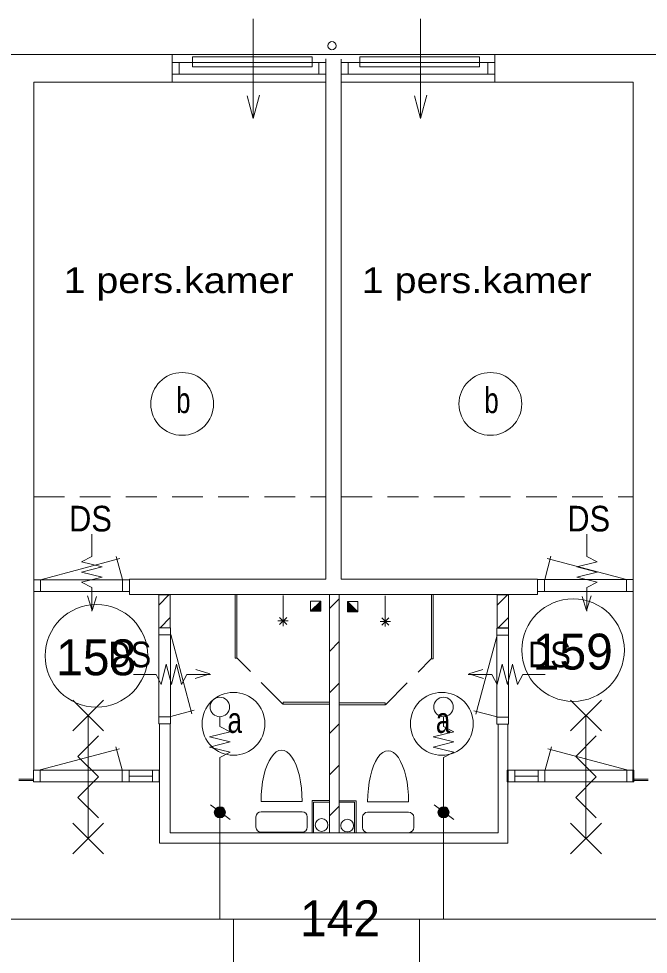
# Model space of a CAD drawing. Extents: x 295824 to 414724, y 24924 to 109024.
# Drawn here: x 313944 to 320086, y 70382 to 79510 of the extents above; entities that cross this region are included whole.
import ezdxf
from ezdxf.enums import TextEntityAlignment as Align

# ---------------------------------------------------------------- set-up
doc = ezdxf.new("R2010")
doc.units = 0
doc.header["$LTSCALE"] = 100
doc.linetypes.add('MEDIUM_DASHED', pattern=[4.5, 3, -1.5])
for name, color, linetype, lineweight in [('1', 7, 'Continuous', 13), ('16', 7, 'Continuous', 13), ('24', 7, 'Continuous', 13), ('61', 7, 'Continuous', 13)]:
    doc.layers.add(name, color=color, linetype=linetype, lineweight=lineweight)

msp = doc.modelspace()

# ---------------------------------------------------------------- hatches: boundary and pattern name
at = {"layer": '24'}
for points in [[(315960.8, 71768.1, 1), (315852.2, 71768.1, 1)], [(318142.8, 71768.1, 1), (318034.2, 71768.1, 1)]]:
    msp.add_hatch(color=256, dxfattribs=at).paths.add_polyline_path(points)
at = {"layer": '61'}
for points in [[(316790.6, 73728.2), (316890.6, 73828.2), (316890.6, 73728.2)], [(317253, 73722.8), (317153, 73822.8), (317153, 73722.8)]]:
    msp.add_hatch(color=256, dxfattribs=at).paths.add_polyline_path(points)

# ---------------------------------------------------------------- linework, layer by layer
at = {"layer": '1'}
for p, q in [((315906.5, 71736.8), (315906.5, 70726.3)), ((318088.5, 71730.1), (318088.5, 70726.3)), ((316039.8, 69843.4), (316039.8, 70726.3)), ((317855.3, 69838.4), (317855.3, 70726.3))]:
    msp.add_line(p, q, dxfattribs=at)
at = {"layer": '16'}
for p, q in [((314557.3, 74111.7), (314757.3, 74161.7)), ((319587.6, 74111.7), (319387.6, 74161.7)), ((315433.7, 73013.5), (315383.7, 73213.5)), ((318711.2, 73013.5), (318761.2, 73213.5))]:
    msp.add_line(p, q, dxfattribs=at)
at = {"layer": '24'}
for p, q in [((316231.3, 78534.5), (316171.7, 78756.9)), ((317863.6, 78534.5), (317804, 78756.9)), ((314660.7, 73736.3), (314615.7, 73880.4)), ((314703.1, 73872.1), (314660.7, 73736.3)), ((319441.8, 73872.1), (319484.2, 73736.3)), ((319484.2, 73736.3), (319529.2, 73880.4)), ((315809.1, 73116.9), (315665, 73071.9)), ((315673.3, 73159.3), (315809.1, 73116.9)), ((318471.6, 73159.3), (318335.8, 73116.9)), ((318335.8, 73116.9), (318480, 73071.9)), ((315906.5, 72253.5), (315906.5, 71714.1)), ((318088.5, 72253.5), (318088.5, 71745.1)), ((315814.9, 71838.9), (316006.4, 71697.3)), ((317996.9, 71838.9), (318188.4, 71697.3)), ((304097.2, 70726.3), (328693.9, 70726.3))]:
    msp.add_line(p, q, dxfattribs=at)
for points in [[(316231.3, 79509.5), (316231.3, 78534.5), (316293, 78764.7)], [(317863.6, 79509.5), (317863.6, 78534.5), (317925.3, 78764.7)], [(314757.3, 74161.7), (314557.3, 74211.7), (314657.3, 74261.7), (314657.3, 74480.4)], [(319387.6, 74161.7), (319587.6, 74211.7), (319487.6, 74261.7), (319487.6, 74480.4)], [(314657.3, 73730.4), (314657.3, 73961.7), (314557.3, 74011.7), (314757.3, 74061.7), (314557.3, 74111.7)], [(319487.6, 73730.4), (319487.6, 73961.7), (319587.6, 74011.7), (319387.6, 74061.7), (319587.6, 74111.7)], [(315383.7, 73213.5), (315333.7, 73013.5), (315283.7, 73113.5), (315065, 73113.5)], [(315815, 73113.5), (315583.7, 73113.5), (315533.7, 73013.5), (315483.7, 73213.5), (315433.7, 73013.5)], [(318330, 73113.5), (318561.2, 73113.5), (318611.2, 73013.5), (318661.2, 73213.5), (318711.2, 73013.5)], [(318761.2, 73213.5), (318811.2, 73013.5), (318861.2, 73113.5), (319079.9, 73113.5)], [(315906.5, 72703.5), (315906.5, 72603.5), (316006.5, 72553.5), (315806.5, 72503.5), (316006.5, 72453.5), (315806.5, 72403.5), (316006.5, 72353.5), (315906.5, 72303.5), (315906.5, 72253.5)], [(318088.5, 72703.5), (318088.5, 72603.5), (318188.5, 72553.5), (317988.5, 72503.5), (318188.5, 72453.5), (317988.5, 72403.5), (318188.5, 72353.5), (318088.5, 72303.5), (318088.5, 72253.5)]]:
    msp.add_lwpolyline(points, dxfattribs=at)
for points in [[(315640, 79038.7), (316805.9, 79038.7), (316805.9, 79138.7), (315640, 79138.7)], [(317272.3, 79038.7), (318438.2, 79038.7), (318438.2, 79138.7), (317272.3, 79138.7)]]:
    msp.add_lwpolyline(points, close=True, dxfattribs=at)
for centre, radius in [((315906.5, 72795.2), 95), ((318088.5, 72795.2), 95), ((315906.5, 71768.1), 54.3), ((318088.5, 71768.1), 54.3)]:
    msp.add_circle(centre, radius, dxfattribs=at)
at = {"layer": '61'}
for p, q in [((315441, 78890.7), (315441, 79160.7)), ((318589.5, 78890.8), (318589.5, 79160.8)), ((315508, 78969), (315508, 79082.9)), ((316873.1, 78968.4), (316873.1, 79082.4)), ((316940.1, 79118.1), (316940.1, 74040.8)), ((317090.1, 79114.3), (317090.1, 74040.8)), ((317156.6, 78969.4), (317156.6, 79083.4)), ((318520.9, 78969.1), (318520.9, 79082.7)), ((314090.1, 78890.8), (316940.1, 78890.8)), ((314090.1, 72179.8), (314090.1, 78890.8)), ((319940.1, 78890.8), (317090.1, 78890.8)), ((319940.1, 72179.8), (319940.1, 78890.8)), ((314157.5, 74036.8), (314930.2, 74243.8)), ((314955.9, 74037.4), (314895.1, 74264.3)), ((319075.3, 74038.5), (319136, 74265.4)), ((319873.7, 74037.9), (319100.9, 74244.9)), ((314158.2, 73922.2), (314158.2, 74036.2)), ((314958.2, 73922.2), (314958.2, 74036.2)), ((315025.2, 73922.2), (315025.2, 74036.2)), ((319005.9, 73923.2), (319005.9, 74037.2)), ((319072.9, 73923.2), (319072.9, 74037.2)), ((319872.9, 73923.2), (319872.9, 74037.2)), ((315310.4, 73789.9), (315410.1, 73889.6)), ((315311.9, 73566.1), (315311.9, 73890.2)), ((315311.9, 73890.2), (315421.9, 73890.2)), ((315421.9, 73566.1), (315421.9, 73890.2)), ((316073.1, 73890.5), (316073.1, 73270)), ((316523, 73684), (316523, 73884)), ((316975, 73890.8), (316975, 71565.8)), ((316975.5, 73754.6), (317071.3, 73850.4)), ((317071.3, 73890.8), (317071.3, 71565.8)), ((317520.7, 73678.6), (317520.7, 73878.6)), ((317970.5, 73885.1), (317970.5, 73264.6)), ((318610.9, 73566.1), (318610.9, 73890.2)), ((318610.9, 73890.2), (318720.8, 73890.2)), ((318612.6, 73789.9), (318712.3, 73889.6)), ((318720.8, 73566.1), (318720.8, 73890.2)), ((315322.7, 73567.3), (315422.4, 73667)), ((316558.3, 73669.3), (316487.6, 73598.6)), ((316558.3, 73598.6), (316487.6, 73669.3)), ((316523, 73684), (316523, 73584)), ((317485.3, 73664), (317556, 73593.3)), ((317485.3, 73593.3), (317556, 73664)), ((317520.7, 73678.6), (317520.7, 73578.6)), ((318621.2, 73567.3), (318720.9, 73667)), ((315310.1, 73565.2), (315310.1, 72632.8)), ((315311.9, 73566.1), (315421.9, 73566.1)), ((316573, 73634), (316473, 73634)), ((317470.7, 73628.6), (317570.7, 73628.6)), ((318610.9, 73566.1), (318720.8, 73566.1)), ((315310.1, 73499.8), (315424.1, 73499.8)), ((315427.3, 73500.6), (315634.3, 72727.8)), ((318611.5, 73496.3), (318404.4, 72723.6)), ((318723.6, 73495.6), (318609.6, 73495.6)), ((318610.2, 73562.6), (318724.2, 73562.6)), ((318723.6, 73562.6), (318723.6, 72628.6)), ((316975.5, 73336.5), (317071.3, 73432.3)), ((316975.5, 72931.9), (317071.3, 73027.7)), ((314772.1, 72863), (314472.1, 72563)), ((314472.1, 72863), (314772.1, 72563)), ((316973.2, 72840.5), (316524, 72840.5)), ((316524, 72822.5), (316524, 72840.5)), ((317070.5, 72835.1), (317519.6, 72835.1)), ((317519.6, 72817.1), (317519.6, 72835.1)), ((319628, 72863), (319328, 72563)), ((319328, 72863), (319628, 72563)), ((315427.9, 72702.2), (315654.8, 72762.9)), ((316973.5, 72822.5), (316524, 72822.5)), ((317070.2, 72817.1), (317519.6, 72817.1)), ((318610.9, 72697.9), (318384, 72758.7)), ((314622.1, 71513), (314622.1, 72713)), ((315310.1, 72699.8), (315424.1, 72699.8)), ((318723.6, 72695.6), (318609.6, 72695.6)), ((319478, 71513), (319478, 72713)), ((315316.1, 72629.2), (315316.1, 72063.4)), ((315316.1, 72629.2), (315421.3, 72629.2)), ((316975.5, 72535.9), (317071.3, 72631.7)), ((318621.3, 72627.8), (318621.3, 71565.8)), ((318621.3, 72627.8), (318716.1, 72627.8)), ((318716.1, 72627.8), (318716.1, 72165.8)), ((314154.1, 72180.4), (314926.8, 72387.5)), ((314952.5, 72181), (314891.7, 72407.9)), ((319079.8, 72181.1), (319140.6, 72407.9)), ((319878.3, 72180.4), (319105.5, 72387.5)), ((316975.5, 72132.6), (317071.3, 72228.3)), ((314154.9, 72065.8), (314154.9, 72179.8)), ((314954.9, 72065.8), (314954.9, 72179.8)), ((315021.9, 72065.8), (315021.9, 72179.8)), ((315247.9, 72119.9), (315021.9, 72119.9)), ((315247.9, 72065.8), (315247.9, 72179.8)), ((318784.5, 72065.8), (318784.5, 72179.8)), ((318784.5, 72119.9), (319010.5, 72119.9)), ((319010.5, 72065.8), (319010.5, 72179.8)), ((319077.5, 72065.8), (319077.5, 72179.8)), ((319877.5, 72065.8), (319877.5, 72179.8)), ((313944.8, 72092.1), (314086, 72092.1)), ((313944.8, 72077.1), (314086, 72077.1)), ((319943.6, 72092.1), (320084.8, 72092.1)), ((319943.6, 72077.1), (320084.8, 72077.1)), ((316708.7, 71873.6), (316308.7, 71873.6)), ((316821.2, 71866.2), (316971.2, 71866.2)), ((316821.2, 71566.2), (316821.2, 71866.2)), ((317071.3, 71865.8), (317221.3, 71865.8)), ((317221.3, 71865.8), (317221.3, 71565.8)), ((317748.1, 71868.7), (317348.1, 71868.7)), ((316308.7, 71773.6), (316708.7, 71773.6)), ((316975.5, 71731.7), (317071.3, 71827.4)), ((317348.1, 71768.7), (317748.1, 71768.7)), ((314772.1, 71663), (314472.1, 71363)), ((314472.1, 71663), (314772.1, 71363)), ((316258.7, 71623.6), (316258.7, 71723.6)), ((316758.7, 71723.6), (316758.7, 71623.6)), ((317298.1, 71618.7), (317298.1, 71718.7)), ((317798.1, 71718.7), (317798.1, 71618.7)), ((319628, 71663), (319328, 71363)), ((319328, 71663), (319628, 71363)), ((316708.7, 71573.6), (316308.7, 71573.6)), ((317748.1, 71568.7), (317348.1, 71568.7))]:
    msp.add_line(p, q, dxfattribs=at)
at = {"layer": '61', "linetype": 'MEDIUM_DASHED'}
for p, q in [((314090.7, 74844.1), (316939.8, 74844.1)), ((317093.1, 74844.1), (319940.1, 74844.1)), ((316522, 72822.9), (316075.1, 73269.8)), ((317521.7, 72817.6), (317968.6, 73264.5))]:
    msp.add_line(p, q, dxfattribs=at)
at = {"layer": '61'}
for points in [[(301796.6, 66927.7), (301820.1, 79160.8), (332210.1, 79160.8)], [(314091.2, 73922.2), (314091.2, 74036.2), (315025.2, 74036.2)], [(315025.2, 73922.2), (314091.2, 73922.2), (314091.2, 74036.2)], [(316941.1, 74040.8), (315026, 74040.8), (315026, 73890.8), (319005.4, 73890.8)], [(317091.1, 74040.8), (319005.4, 74040.8), (319005.4, 73890.8)], [(319939.9, 73923.2), (319939.9, 74037.2), (319005.9, 74037.2)], [(319005.9, 73923.2), (319939.9, 73923.2), (319939.9, 74037.2)], [(316055.1, 73890.5), (316055.1, 73270), (316073.1, 73270)], [(317988.5, 73885.1), (317988.5, 73264.6), (317970.5, 73264.6)], [(316890.6, 73828.2), (316890.6, 73728.2), (316790.6, 73728.2)], [(317153, 73822.8), (317153, 73722.8), (317253, 73722.8)], [(315421.3, 72629.2), (315421.3, 71565.8), (318621.3, 71565.8)], [(314722.1, 71713), (314522.1, 71913), (314722.1, 72113), (314522.1, 72313), (314722.1, 72513)], [(319578, 71713), (319378, 71913), (319578, 72113), (319378, 72313), (319578, 72513)], [(315316.1, 72065.8), (315316.1, 71465.8), (318716.1, 71465.8), (318716.1, 72065.8)], [(316806.2, 71566.2), (316806.2, 71881.2), (316971.2, 71881.2)], [(317071.3, 71880.8), (317236.3, 71880.8), (317236.3, 71565.8)]]:
    msp.add_lwpolyline(points, dxfattribs=at)
for points in [[(315441.2, 78968.9), (315441.2, 79082.9), (316939.9, 79082.9), (316939.9, 78968.9)], [(317090.2, 78969.1), (317090.2, 79083.1), (318589.6, 79083.1), (318589.6, 78969.1)], [(316890.6, 73828.2), (316790.6, 73828.2), (316790.6, 73728.2)], [(316790.6, 73728.2), (316890.6, 73828.2), (316890.6, 73728.2)], [(317153, 73822.8), (317253, 73822.8), (317253, 73722.8)], [(317253, 73722.8), (317153, 73822.8), (317153, 73722.8)], [(315310.1, 72631.9), (315424.1, 72631.9), (315424.1, 73565.9), (315310.1, 73565.9)], [(318723.6, 73562.6), (318723.6, 72628.6), (318609.6, 72628.6), (318609.6, 73562.6)], [(314087.9, 72065.8), (314087.9, 72179.8), (315314.2, 72179.8), (315314.2, 72065.8)], [(314087.9, 72065.8), (314087.9, 72179.8), (315314.2, 72179.8), (315314.2, 72065.8)], [(318709.2, 72065.8), (318709.2, 72179.8), (319936.2, 72179.8), (319936.2, 72065.8)], [(318717.5, 72065.8), (318717.5, 72179.8), (319944.5, 72179.8), (319944.5, 72065.8)]]:
    msp.add_lwpolyline(points, close=True, dxfattribs=at)
for centre, radius in [((317000.1, 79245.8), 40), ((315538.5, 75751.7), 306.3), ((318545.3, 75751.7), 306.3), ((319352.5, 73350.1), 500), ((314703, 73294.4), 500), ((316039.7, 72631.2), 306.3), ((318072, 72631.2), 306.3), ((316898.8, 71643.7), 62.5), ((317148.8, 71638.2), 62.5)]:
    msp.add_circle(centre, radius, dxfattribs=at)
for centre, start, end in [((316308.7, 71723.6), 90, 180), ((316708.7, 71723.6), 0, 90), ((317348.1, 71718.7), 90, 180), ((317748.1, 71718.7), 0, 90), ((316308.7, 71623.6), 180, 270), ((316708.7, 71623.6), 270, 0), ((317348.1, 71618.7), 180, 270), ((317748.1, 71618.7), 270, 0)]:
    msp.add_arc(centre, 50, start, end, dxfattribs=at)
for centre in [(316508.7, 71873.6), (317548.1, 71868.7)]:
    msp.add_ellipse(centre, major_axis=(0, 500), ratio=0.4, start_param=4.712389, end_param=7.853982, dxfattribs=at)

# ---------------------------------------------------------------- texts
at = {"layer": '24', "width": 0.9}
for p in [(314435.5, 74507.5), (319296.1, 74507.5), (314818.6, 73182.5), (318913, 73182.5)]:
    msp.add_text('DS', height=250, dxfattribs=at).set_placement(p)
at = {"layer": '61'}
for s, width, p in [('1 pers.kamer', 1.15, (314381.4, 76832.7)), ('1 pers.kamer', 1.15, (317290.6, 76832.7)), ('b', 0.75, (315480.5, 75662.5)), ('b', 0.75, (318487.3, 75662.5)), ('a', 0.75, (315981.7, 72542)), ('a', 0.75, (318014, 72542))]:
    msp.add_text(s, height=250, dxfattribs=dict(at, width=width)).set_placement(p)
for s, p in [('159', (319349.6, 73160.2)), ('158', (314700.1, 73104.5)), ('142', (317079.2, 70558.3))]:
    msp.add_text(s, height=350, dxfattribs=at).set_placement(p, align=Align.CENTER)

doc.saveas('drawing.dxf')
